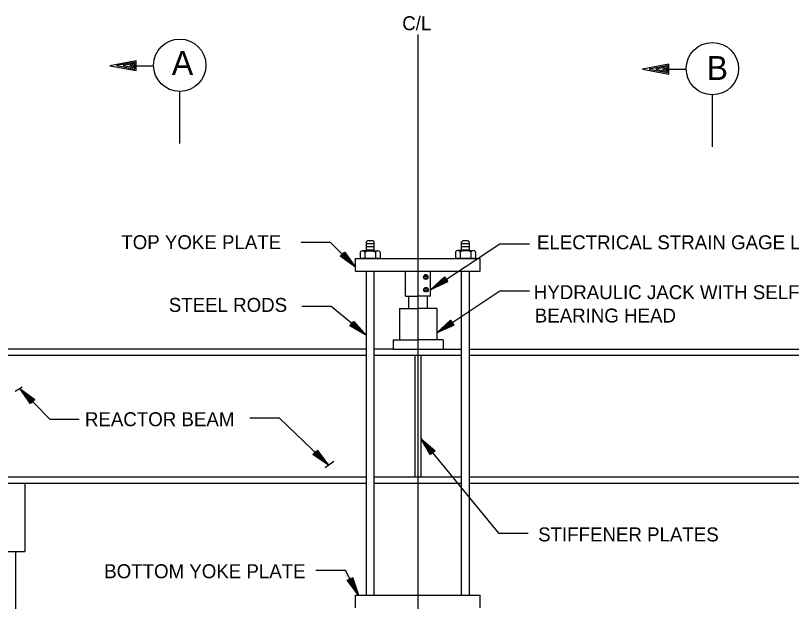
# Model space of a CAD drawing. Extents: x 22369.6 to 22413.6, y 22369.6 to 22403.6.
# Drawn here: x 22376.09 to 22383.87, y 22380.25 to 22386.12 of the extents above; entities that cross this region are included whole.
import ezdxf

# ---------------------------------------------------------------- set-up
doc = ezdxf.new("R2010")
doc.units = 0
for name, color, linetype in [('Level 1', 7, 'Continuous'), ('Level 2', 7, 'Continuous'), ('Level 3', 7, 'Continuous'), ('Level 4', 7, 'Continuous'), ('Level 7', 7, 'Continuous')]:
    doc.layers.add(name, color=color, linetype=linetype)

msp = doc.modelspace()

# ---------------------------------------------------------------- linework, layer by layer
at = {"layer": 'Level 1'}
for p, q in [((22380.1251, 22385.932), (22380.1251, 22375.9342)), ((22379.6094, 22383.836), (22379.6876, 22383.836)), ((22379.6094, 22383.8047), (22379.6876, 22383.8047)), ((22379.6094, 22383.7735), (22379.6876, 22383.7735)), ((22380.5271, 22383.7637), (22380.6803, 22383.7637)), ((22380.6038, 22383.7637), (22380.5271, 22383.7637)), ((22380.5626, 22383.835), (22380.6407, 22383.835)), ((22380.5626, 22383.8038), (22380.6407, 22383.8038)), ((22380.5626, 22383.7725), (22380.6407, 22383.7725)), ((22379.5484, 22383.7501), (22379.5484, 22383.6876)), ((22379.5484, 22383.6876), (22379.7484, 22383.6876)), ((22379.5717, 22383.7626), (22379.7248, 22383.7626)), ((22379.6484, 22383.7626), (22379.5717, 22383.7626)), ((22379.5952, 22383.7501), (22379.5952, 22383.6876)), ((22379.7015, 22383.7501), (22379.7015, 22383.6876)), ((22379.7484, 22383.7501), (22379.7484, 22383.6876)), ((22380.5038, 22383.7512), (22380.5038, 22383.6887)), ((22380.5038, 22383.6887), (22380.7038, 22383.6887)), ((22380.5507, 22383.7512), (22380.5507, 22383.6887)), ((22380.6569, 22383.7512), (22380.6569, 22383.6887)), ((22380.7038, 22383.7512), (22380.7038, 22383.6887)), ((22379.4632, 22383.6354), (22379.4632, 22383.6354)), ((22379.5001, 22383.5987), (22379.5001, 22383.5987)), ((22379.6876, 22380.3087), (22379.6876, 22383.5587)), ((22380.5626, 22380.3087), (22380.5626, 22383.5584)), ((22380.2967, 22383.4011), (22380.2967, 22383.4011)), ((22380.2534, 22383.3723), (22380.2534, 22383.3723)), ((22379.5693, 22382.9469), (22379.5693, 22382.9469)), ((22379.6094, 22382.9139), (22379.6094, 22382.9139)), ((22380.3159, 22382.9382), (22380.3159, 22382.9382)), ((22380.3591, 22382.9672), (22380.3591, 22382.9672)), ((22376.09, 22382.3536), (22376.1598, 22382.3986)), ((22376.1357, 22382.3831), (22376.1357, 22382.3831)), ((22376.172, 22382.3458), (22376.172, 22382.3458)), ((22380.1563, 22381.8814), (22380.1563, 22381.8814)), ((22380.1893, 22381.8411), (22380.1893, 22381.8411)), ((22379.1912, 22381.6482), (22379.1912, 22381.6482)), ((22379.1969, 22381.589), (22379.2846, 22381.6529)), ((22379.2286, 22381.6121), (22379.2286, 22381.6121)), ((22379.5054, 22380.3549), (22379.5054, 22380.3549)), ((22379.5293, 22380.3087), (22379.5293, 22380.3087))]:
    msp.add_line(p, q, dxfattribs=at)
for points in [[(22379.5001, 22383.5987), (22379.2517, 22383.8456), (22378.9553, 22383.8456)], [(22380.2534, 22383.3723), (22380.9479, 22383.8326), (22381.2442, 22383.8326)], [(22379.3893, 22383.7525), (22379.5001, 22383.5987), (22379.3456, 22383.7086), (22379.383, 22383.7462), (22379.4632, 22383.6354), (22379.3584, 22383.71), (22379.3823, 22383.7341), (22379.4278, 22383.6706), (22379.3711, 22383.7115), (22379.3809, 22383.7214), (22379.3909, 22383.7073)], [(22380.4264, 22383.4498), (22380.2534, 22383.3723), (22380.3922, 22383.5015), (22380.4214, 22383.4573), (22380.2967, 22383.4011), (22380.391, 22383.4887), (22380.4098, 22383.4604), (22380.3384, 22383.4287), (22380.3899, 22383.476), (22380.3976, 22383.4643), (22380.3818, 22383.4574)], [(22380.3159, 22382.9382), (22380.9487, 22383.362), (22381.2451, 22383.362)], [(22379.6094, 22382.9139), (22379.2577, 22383.2034), (22378.9613, 22383.2034)], [(22380.4885, 22383.0165), (22380.3159, 22382.9382), (22380.454, 22383.0681), (22380.4835, 22383.024), (22380.3591, 22382.9672), (22380.4529, 22383.0553), (22380.4719, 22383.027), (22380.4007, 22382.995), (22380.4519, 22383.0425), (22380.4597, 22383.0309), (22380.4439, 22383.0239)], [(22379.4847, 22383.0566), (22379.6094, 22382.9139), (22379.4453, 22383.0088), (22379.479, 22383.0497), (22379.5693, 22382.9469), (22379.4579, 22383.0114), (22379.4795, 22383.0377), (22379.5307, 22382.9787), (22379.4704, 22383.0141), (22379.4793, 22383.0249), (22379.4905, 22383.0117)], [(22376.1357, 22382.3831), (22376.4364, 22382.0748), (22376.7327, 22382.0748)], [(22376.2441, 22382.2276), (22376.1357, 22382.3831), (22376.2884, 22382.2708), (22376.2505, 22382.2338), (22376.172, 22382.3458), (22376.2757, 22382.2696), (22376.2514, 22382.2458), (22376.2069, 22382.31), (22376.2629, 22382.2683), (22376.2529, 22382.2586), (22376.2432, 22382.2728)], [(22379.2286, 22381.6121), (22378.7381, 22382.0847), (22378.4418, 22382.0847)], [(22380.1563, 22381.8814), (22380.9341, 22380.9323), (22381.2305, 22380.9323)], [(22380.2509, 22381.7171), (22380.1563, 22381.8814), (22380.2988, 22381.7564), (22380.2578, 22381.7228), (22380.1893, 22381.8411), (22380.286, 22381.7562), (22380.2597, 22381.7347), (22380.221, 22381.8025), (22380.2732, 22381.7561), (22380.2624, 22381.7472), (22380.2539, 22381.7622)], [(22379.1154, 22381.7642), (22379.2286, 22381.6121), (22379.0724, 22381.7196), (22379.1092, 22381.7577), (22379.1912, 22381.6482), (22379.0851, 22381.7212), (22379.1087, 22381.7457), (22379.1552, 22381.6829), (22379.0978, 22381.7229), (22379.1075, 22381.7329), (22379.1177, 22381.719)], [(22379.5293, 22380.3087), (22379.4007, 22380.5566), (22379.1044, 22380.5566)], [(22379.4707, 22380.489), (22379.5293, 22380.3087), (22379.4157, 22380.4605), (22379.4627, 22380.4849), (22379.5054, 22380.3549), (22379.4282, 22380.458), (22379.4584, 22380.4736), (22379.4823, 22380.3993), (22379.4408, 22380.4555), (22379.4532, 22380.4619), (22379.4584, 22380.4454)]]:
    msp.add_lwpolyline(points, dxfattribs=at)
for centre, radius, start, end in [((22379.725, 22383.7345), 0.0282, 33.63855, 146.36145), ((22380.5273, 22383.7354), 0.0283, 33.95545, 146.04455), ((22380.6038, 22383.6445), 0.1192, 63.54903, 116.45096), ((22380.6804, 22383.7354), 0.0283, 33.96599, 146.03402), ((22379.5718, 22383.7344), 0.0282, 33.86032, 146.13968), ((22379.6484, 22383.6433), 0.1193, 63.55276, 116.44724)]:
    msp.add_arc(centre, radius, start, end, dxfattribs=at)
at = {"layer": 'Level 2'}
for p, q in [((22379.6094, 22383.8516), (22379.6251, 22383.8672)), ((22379.6094, 22383.7626), (22379.6094, 22383.8516)), ((22379.6251, 22383.8672), (22379.6719, 22383.8672)), ((22379.6876, 22383.8516), (22379.6719, 22383.8672)), ((22379.6876, 22383.7636), (22379.6876, 22383.8516)), ((22380.5626, 22383.8506), (22380.5782, 22383.8663)), ((22380.5626, 22383.7638), (22380.5626, 22383.8506)), ((22380.5782, 22383.8663), (22380.6251, 22383.8663)), ((22380.6251, 22383.8663), (22380.6407, 22383.8506)), ((22380.6407, 22383.8506), (22380.6407, 22383.763)), ((22379.6094, 22380.3087), (22379.6094, 22383.5587)), ((22380.6407, 22383.5589), (22380.6407, 22380.3087)), ((22380.2282, 22383.505), (22380.1847, 22383.505)), ((22380.2271, 22383.4894), (22380.1852, 22383.4894)), ((22380.2117, 22383.5206), (22380.1956, 22383.5206)), ((22380.2286, 22383.38), (22380.1855, 22383.38)), ((22380.2293, 22383.3644), (22380.1856, 22383.3644)), ((22380.0938, 22382.715), (22380.0938, 22381.4962)), ((22380.1563, 22382.715), (22380.1563, 22381.4962))]:
    msp.add_line(p, q, dxfattribs=at)
for centre in [(22380.2061, 22383.4987), (22380.2072, 22383.3717)]:
    msp.add_circle(centre, 0.023, dxfattribs=at)
at = {"layer": 'Level 3'}
for p, q in [((22377.3022, 22385.618), (22377.4772, 22385.618)), ((22382.6398, 22385.5835), (22382.8148, 22385.5835)), ((22377.7397, 22384.8396), (22377.7397, 22385.3559)), ((22383.0773, 22384.8051), (22383.0773, 22385.3214))]:
    msp.add_line(p, q, dxfattribs=at)
for points in [[(22377.3022, 22385.6547), (22377.3022, 22385.6679), (22377.0397, 22385.618), (22377.3022, 22385.569), (22377.3022, 22385.6547), (22377.1067, 22385.6189), (22377.2896, 22385.5839), (22377.2896, 22385.6404), (22377.1727, 22385.6189), (22377.2773, 22385.5992), (22377.2773, 22385.6255), (22377.2397, 22385.6189), (22377.2646, 22385.6141)], [(22382.6398, 22385.6202), (22382.6398, 22385.6334), (22382.3773, 22385.5835), (22382.6398, 22385.5345), (22382.6398, 22385.6202), (22382.4443, 22385.5844), (22382.6271, 22385.5494), (22382.6271, 22385.6059), (22382.5103, 22385.5844), (22382.6149, 22385.5647), (22382.6149, 22385.591), (22382.5773, 22385.5844), (22382.6021, 22385.5796)]]:
    msp.add_lwpolyline(points, dxfattribs=at)
for centre in [(22377.7397, 22385.623), (22383.0773, 22385.5885)]:
    msp.add_circle(centre, 0.2625, dxfattribs=at)
at = {"layer": 'Level 7'}
for p, q in [((22379.5001, 22383.6837), (22380.7501, 22383.6837)), ((22379.5001, 22383.5587), (22379.5001, 22383.6837)), ((22380.7501, 22383.5587), (22380.7501, 22383.6837)), ((22379.5001, 22383.5587), (22380.7501, 22383.5587)), ((22380.0034, 22383.3087), (22380.0034, 22383.5587)), ((22380.2534, 22383.3087), (22380.2534, 22383.5587)), ((22380.0034, 22383.3087), (22380.1284, 22383.3087)), ((22380.0346, 22383.1837), (22380.0346, 22383.3087)), ((22380.2534, 22383.3087), (22380.1284, 22383.3087)), ((22380.2221, 22383.1837), (22380.2221, 22383.3087)), ((22379.9409, 22383.1837), (22380.1284, 22383.1837)), ((22379.9409, 22383.1837), (22379.9409, 22382.8712)), ((22380.3159, 22383.1837), (22380.1284, 22383.1837)), ((22380.3159, 22383.1837), (22380.3159, 22382.8712)), ((22379.8784, 22382.8712), (22380.1284, 22382.8712)), ((22379.8784, 22382.8712), (22379.8784, 22382.7775)), ((22380.3784, 22382.8712), (22380.1284, 22382.8712)), ((22380.3784, 22382.8712), (22380.3784, 22382.7775)), ((22379.6094, 22382.7775), (22375.5001, 22382.7775)), ((22379.8784, 22382.7775), (22379.6876, 22382.7775)), ((22379.8784, 22382.7775), (22380.5626, 22382.7775)), ((22380.6407, 22382.7775), (22384.7501, 22382.7775)), ((22375.5001, 22382.715), (22379.6094, 22382.715)), ((22379.6876, 22382.715), (22380.5626, 22382.715)), ((22380.6407, 22382.715), (22384.7501, 22382.715)), ((22375.5001, 22381.4337), (22376.1876, 22381.4337)), ((22375.8751, 22381.4962), (22379.6094, 22381.4962)), ((22376.1876, 22381.4337), (22376.1876, 22380.7462)), ((22376.1876, 22381.4337), (22379.6094, 22381.4337)), ((22379.6876, 22381.4962), (22380.5626, 22381.4962)), ((22379.6876, 22381.4337), (22380.5626, 22381.4337)), ((22380.6407, 22381.4962), (22384.3751, 22381.4962)), ((22380.6407, 22381.4337), (22384.0626, 22381.4337)), ((22375.5001, 22380.7462), (22376.1876, 22380.7462)), ((22376.0938, 22380.7462), (22376.0938, 22378.4337)), ((22379.5001, 22380.3087), (22380.7501, 22380.3087)), ((22379.5001, 22380.1837), (22379.5001, 22380.3087)), ((22380.7501, 22380.1837), (22380.7501, 22380.3087))]:
    msp.add_line(p, q, dxfattribs=at)

# ---------------------------------------------------------------- texts
at = {"layer": 'Level 3'}
for s, p in [('A', (22377.66, 22385.5262)), ('B', (22383.0195, 22385.4754))]:
    msp.add_text(s, height=0.2398, dxfattribs=at).set_placement(p)
at = {"layer": 'Level 4'}
for s, p in [('C/L', (22379.969, 22385.9739)), ('TOP YOKE PLATE', (22377.1537, 22383.779)), ('ELECTRICAL STRAIN GAGE LOAD CELL', (22381.3191, 22383.7774)), ('HYDRAULIC JACK WITH SELF LEVELING', (22381.2879, 22383.2775)), ('STEEL RODS', (22377.6294, 22383.1498)), ('BEARING HEAD', (22381.2976, 22383.0433)), ('REACTOR BEAM', (22376.7891, 22382.0037)), ('STIFFENER PLATES', (22381.3311, 22380.8487)), ('BOTTOM YOKE PLATE', (22376.9825, 22380.4796))]:
    msp.add_text(s, height=0.14, dxfattribs=at).set_placement(p)

doc.saveas('drawing.dxf')
